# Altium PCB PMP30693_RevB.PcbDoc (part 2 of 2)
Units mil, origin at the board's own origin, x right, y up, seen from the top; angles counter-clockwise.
Board outline 2800 x 2253.94 mil, 2 copper layers (Top Layer, Bottom Layer), stack 62 mil thick; 97 components, 41 nets, 215 pads, 48 vias.
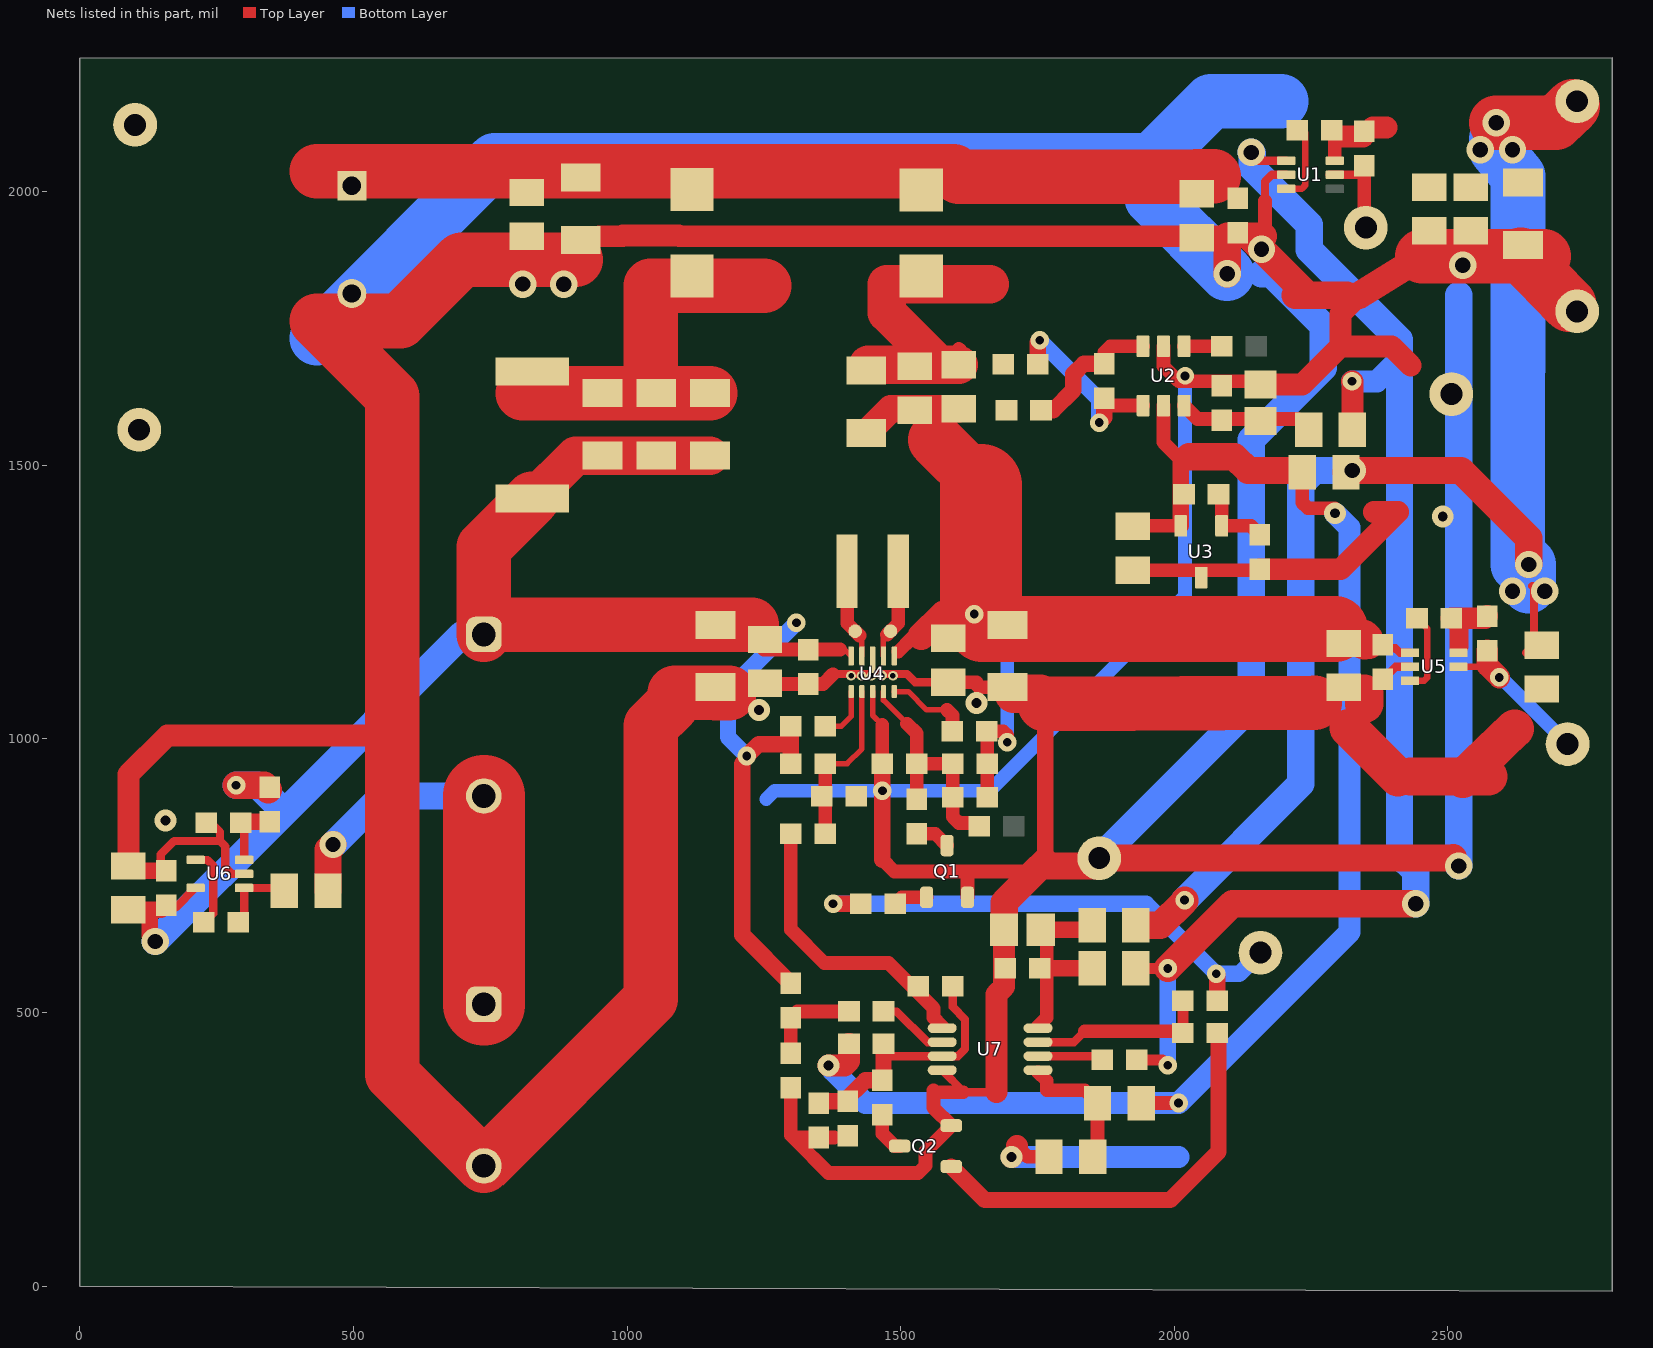
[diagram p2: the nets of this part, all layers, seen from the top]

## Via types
v1: diameter 34, hole 16, Top Layer to Bottom Layer, 18 vias
v2: diameter 50, hole 28, Top Layer to Bottom Layer, 17 vias
v3: diameter 40, hole 18, Top Layer to Bottom Layer, 7 vias
v4: diameter 18, hole 10, Top Layer to Bottom Layer, 5 vias
v5: diameter 32, hole 16, Top Layer to Bottom Layer, 1 vias

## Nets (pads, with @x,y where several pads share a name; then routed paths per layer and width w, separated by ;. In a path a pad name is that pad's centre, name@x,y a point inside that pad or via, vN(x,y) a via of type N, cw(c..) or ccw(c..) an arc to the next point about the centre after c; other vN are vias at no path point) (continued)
GND: C1.2 C2.2 C3.2 C4.2 C5.2 C6.2 C7.2 C8.2 C9.2 C10.2 C12.2 C13.2 C14.2 C15.2 C18.2 C19.2 C20.2 C21.2 C22.2 C23.2 C24.2 C25.2 C26.2 C27.2 C28.2 C29.2 Q1.2 Q2.2 R12.1 R28.1 R30.1 R32.2 R35.1 R38.1 TP4.1 TP5.1 TP6.1 TP11.1 U1.2 U2.2 U3.3 U4.3 U4.8 U5.2 U6.2 U7.4 | length 18373.7
  Top Layer w10: U4.3@1448.82,1086.61 1448.82,1043.31 1466.54,1025.59
  Top Layer w15: C19.2@147.64,759.21 147.64,788.74 172.24,813.35 255.91,813.35 ; R30.1@244.09,841.89 255.91,830.08 255.91,813.35 ; U6.2@300.2,753.31 277.56,753.31 265.75,765.12 265.75,803.5 255.91,813.35 ; 1376.36,1118.48 1511.44,1118.48 1526.22,1103.7 C21.2@1576.77,1103.7 ; U7.4@1575.79,394.68 1616.14,354.33 1675,354.33 ; 2165.62,1983.58 2165.62,2018.47 2178.38,2031.23 U1.2@2204.54,2031.23 ; C24.2@2381.25,1109.13 2404.01,1131.89 U5.2@2430.71,1131.89
  Top Layer w25: 1207.68,1101.73 C14.2@1251.97,1101.73 1253.31,1100.39 C15.2@1330.71,1100.39 1358.27,1100.39 1376.36,1118.48 ; R35.1@1299.21,362.2 1299.21,275.59 1309.06,265.75 ; 1377.95,271.65 1314.96,271.65 1309.06,265.75 ; 1466.54,779.53 1488.19,757.87 1625.98,757.87 ; R28.1@1466.54,954.72 1466.54,1025.59 ; C21.2@1576.77,1103.7 C21.2@1586.61,1103.7 1637.44,1103.7 cw(c1637.44,1102.36) 1638.78,1102.36 ccw(c1646.65,1102.36) 1646.65,1094.49 C22.2@1694.88,1094.49 ; 1614.17,354.33 1563.78,354.33 1560.04,358.07 1560.04,325.79 Q2.2@1592.52,293.31 1545.28,246.06 1545.28,219.88 1532.09,206.69 1368.11,206.69 1309.06,265.75 ; Q1.2@1622.05,710.63 1622.05,753.94 1625.98,757.87 ; 1712.6,255.91 1732.28,236.22 C29.2@1771.02,236.22 ; 1745.66,757.87 1625.98,757.87 ; C12.2@1923.86,1308.43 2154.88,1308.43 R12.1@2156.5,1310.04 ; U2.2@1980.31,1717.52 1980.31,1681.1 2007.87,1653.54 2151.57,1653.54 C9.2@2157.48,1647.64 ; v2@2162.76,1918.66 2165.62,1921.53 2165.62,1983.58
  Top Layer w30: C18.2@88.58,767.72 97.09,759.21 147.64,759.21 C19.2@157.48,759.21 ; 1466.54,779.53 v1(1466.54,905.51) R28.1@1466.54,954.72 ; 1755.28,1082.68 1763.78,1074.17 1763.78,1063.89 1763.78,775.99
  Top Layer w40: C18.2@88.58,767.72 88.58,935.04 160.18,1006.63 570.87,1006.63 ; C7.2@949.72,1918.66 991.3,1918.66 992.39,1919.75 1094.22,1919.75 1095.32,1918.66 2096.46,1918.66 ; 1675,354.33 1675,533.27 1688.98,547.24 C27.2@1688.98,651.57 ; v3(1702.76,236.22) 1712.6,246.06 1712.6,255.91 ; R12.1@2156.5,1310.04 2304.13,1310.04 2409.13,1415.04 2364.49,1415.04 ; C9.2@2157.48,1647.64 2233.9,1647.64 2303.78,1717.52 ; 2337.95,1811.02 2303.78,1776.85 2303.78,1717.52 ; 2432.09,1682.44 2397.01,1717.52 2303.78,1717.52
  Top Layer w50: C27.2@1688.98,651.57 1688.98,701.19 1745.66,757.87 1763.78,775.99 ; 1766.73,767.72 TP11.1@1862.82,767.88 ; TP11.1@1862.8,782.09 v2@2509.79,783.18 ; v2(2096.46,1850.39) 2096.46,1918.66 ; v2@2162.76,1918.66 2135.83,1918.66 2243.46,1811.02 ; 2220.96,1811.02 2243.46,1811.02 ; 2315.45,1811.02 2243.46,1811.02 ; 2337.95,1811.02 2453.12,1882.25
  Top Layer w70: C22.2@1706.69,1082.68 1755.28,1082.68 ; 2318.75,1020.1 2408.93,929.92 ; 2346.83,1064.59 2346.83,1082.68 ; 2432.09,931.25 2531.14,931.25 ; 2527.15,927.4 2531.14,931.25 ; 2573.82,931.25 2531.14,931.25 ; 2621.88,1018.75 2531.14,931.25
  Top Layer w100: 905.51,1875.98 697.35,1875.98 585.14,1763.78 433.07,1763.78 570.87,1625.98 570.87,1006.63 570.87,387.11 C25.2@738.19,219.79 1043.31,524.9 1043.31,1023.62 1082.68,1062.99 ; 1087.5,1084.43 1161.37,1084.06 C13.2@1186.07,1083.94 ; 1763.78,1063.89 2256.25,1065.9 ; 2453.12,1882.25 C5.2@2635.47,1882.25 ; C5.2@2633.23,1884.49 C5.2@2635.47,1882.25 ; 2674.94,1882.25 C5.2@2635.47,1882.25 ; TP5.1@2721.88,1793.75 C5.2@2635.47,1882.25
  Bottom Layer w25: 1254.04,889.89 1269.66,905.51 v1(1466.54,905.51) 1663.39,905.51 2019.68,1261.81 v5(2019.68,1663.39)
  Bottom Layer w40: v3(1702.76,236.22) 2007.87,236.22
  Bottom Layer w50: TP11.1@1862.8,782.09 2140.62,1059.92 2140.62,1546.88 2271.88,1678.12 2271.88,1755.37 2176.85,1850.39 2159.38,1850.39 ; v2(2519.68,767.72) 2519.68,1811.02
  Bottom Layer w100: 433.07,1732.28 757.87,2057.09 1958.66,2057.09 ; v2(2096.46,1850.39) 1958.66,1988.19 1958.66,2057.09 ; 2194.88,2165.35 2066.93,2165.35 1958.66,2057.09
  other v2: 809.38,1831.25 884.38,1830.71 2527.15,1865.62 2159.38,1894.83
  other v3: 156.25,850.76 1241.24,1053.12 1638.78,1065.76 2490.62,1406.25
  other v4: 1409.38,1115.58 1428.12,1115.58 1446.88,1115.58 1465.47,1115.85 1485.83,1115.58
NetC9_1: C9.1 C10.1 R1.1 U2.6 | length 246.1
  Top Layer w25: U2.6@2017.72,1609.25 2042.32,1584.65 2225.75,1584.65 R1.1@2245.43,1564.96
NetC11_1: C11.1 R9.2 U2.3 | length 264.4
  Top Layer w25: C11.1@1871.88,1685.63 1871.88,1706.56 1882.84,1717.52 U2.3@1942.91,1717.52
  Top Layer w30: R9.2@1756.33,1600.82 1778.95,1600.82 1815.62,1637.5 1815.62,1666.88 1834.38,1685.63 C11.1@1871.88,1685.63
NetC11_2: C11.2 R4.2 U2.4 | length 365.7
  Top Layer w25: C11.2@1871.88,1622.64 1885.26,1609.25 U2.4@1942.91,1609.25
  Top Layer w30: R4.2@1750.06,1684.72 1750.06,1724.51 v1(1754.03,1728.48) ; v1(1862.82,1578.12) 1862.82,1578.44 1871.88,1587.5 C11.2@1871.88,1622.64
  Bottom Layer w30: v1(1754.03,1728.48) 1862.82,1619.69 v1(1862.82,1578.12)
NetC13_1: C13.1 C14.1 C15.1 C17.1 C18.1 C19.1 R13.1 R14.1 R15.1 R16.1 R19.1 R21.2 R23.2 R25.1 U4.10 U6.5 | length 3416.4
  Top Layer w10: 1389.76,1163.39 1397.64,1163.39 U4.10@1409.45,1151.57
  Top Layer w15: C19.1@175.2,692.28 210.63,727.72 U6.5@211.61,727.72
  Top Layer w25: C14.1@1240.37,1173.01 1250,1163.39 C15.1@1330.71,1163.39 1389.76,1163.39
  Top Layer w30: C18.1@88.58,687.72 127.95,687.72 ; v2(137.8,629.92) 127.95,639.76 127.95,687.72 ; C19.1@157.48,696.22 148.98,687.72 127.95,687.72 ; v1@1210.63,954.72 1210.63,641.73 R23.2@1299.21,553.15 ; v1(1218.75,968.75) 1240.62,990.62 1297.76,990.62 1299.21,989.17 ; R25.1@1299.21,954.72 1299.21,989.17 ; R19.1@1299.21,1023.62 1299.21,989.17
  Top Layer w50: v1(285.43,915.35) 336.61,915.35 R21.2@344.49,907.48
  Top Layer w70: R13.1@826.77,1438.98 905.51,1517.72 R14.1@954.72,1517.72 R15.1@1053.15,1517.72 R16.1@1151.57,1517.72
  Top Layer w100: R13.1@826.77,1438.98 738.19,1350.39 C17.1@738.19,1190.94 cw(c755.91,1190.94) 755.91,1208.66 C13.1@1161.42,1208.66 1227.91,1208.66
  Bottom Layer w30: v1(1218.75,968.75) 1184.38,1003.12 1184.38,1087.5 v1(1309.38,1212.5)
  Bottom Layer w50: v2(137.8,629.92) 374.02,866.14 ; v1(285.43,915.35) 324.8,915.35 374.02,866.14 ; C17.1@738.19,1190.94 698.82,1190.94 374.02,866.14
NetC16_1: C16.1 C21.1 C22.1 C23.1 C24.1 R6.1 R7.1 R8.1 R9.1 R17.2 R20.2 U4.6 U5.1 | length 1990.3
  Top Layer w15: C24.1@2381.25,1172.12 2387.75,1165.62 2404.13,1165.62 2412.28,1157.48 U5.1@2430.71,1157.48
  Top Layer w25: 1495.47,1159.38 1519.8,1183.7 C21.1@1586.61,1183.7 ; R20.2@1657.05,1013.35 1658.2,1012.2 R17.2@1658.2,954.72 C16.1@1658.2,893.7 C16.1@1657.48,894.42 ; R20.2@1657.48,1013.78 1687.35,1013.78 1694.88,1006.25 v1(1694.88,994.09)
  Top Layer w50: R7.1@1437.01,1559.06 1481.65,1603.7 1563.69,1603.7 ; 1537.84,1187.5 1578.46,1228.12 v1(1634.38,1228.12) ; 1563.69,1546.55 1563.69,1603.7 ; R6.1@1606.3,1603.7 1563.69,1603.7 ; 2347.54,1179.76 2356.05,1171.26
  Top Layer w70: 2343.61,1183.7 2347.54,1179.76
  Top Layer w100: 1563.69,1546.55 1646.65,1463.58 ; 1648.62,1200.79 1648.96,1210.28 1649,1211.44 v1@1649.56,1227.59
  Top Layer w120: 1648.62,1200.79 2293.75,1200.79
  Top Layer w150: v1@1646.65,1228.12 1646.65,1463.58
  Bottom Layer w25: v1(1634.38,1228.12) 1694.88,1167.62 v1(1694.88,994.09)
NetC16_2: C16.2 R17.1 R24.1 R28.2 R29.2 U4.4 | length 442.1
  Top Layer w10: U4.4@1468.5,1086.61 1468.5,1070.87 1511.44,1027.93
  Top Layer w25: 1511.44,1027.93 1529.53,1009.84 R28.2@1529.53,954.72 ; R29.2@1529.53,889.76 R28.2@1529.53,954.72 ; R24.1@1643.7,836.61 1633.86,846.46 1606.3,846.46 1595.2,857.55 C16.2@1595.2,893.7 R17.1@1595.2,954.72 R28.2@1529.53,954.72
NetC17_2: C17.2 C25.1 R26.2 | length 781.4
  Top Layer w50: R26.2@453.39,722.44 453.39,797.87 v2(462.6,807.09)
  Top Layer w150: C25.1@738.19,515.06 C17.2@738.19,895.67
  Bottom Layer w50: v2(462.6,807.09) 551.18,895.67 C17.2@738.19,895.67
NetC26_1: C26.1 R36.2 R37.1 R38.2 R39.1 U7.3 | length 485
  Top Layer w15: 1469.88,420.28 U7.3@1575.79,420.28 1604.74,420.28 1617.74,433.27 1617.74,487.6 1595.28,510.06 R37.1@1595.28,548.06
  Top Layer w30: C26.1@1350,334.62 1353.12,337.75 R38.2@1396.88,337.75 ; R38.2@1403.12,337.75 R38.2@1396.88,337.75 ; R36.2@1468.5,442.91 1468.5,377.95 R39.1@1466.54,375.98 1435.11,375.98 R38.2@1396.88,337.75
NetC27_1: C27.1 C28.1 R40.2 R41.2 U7.8 | length 380.4
  Top Layer w25: U7.8@1750.98,475.1 1766.73,490.85 1766.73,580.71 1766.73,640.75 C27.1@1755.91,651.57
  Top Layer w30: C28.1@1753.94,580.71 1766.73,580.71 R41.2@1849.76,580.71 ; C27.1@1755.91,651.57 1841.89,651.57 R40.2@1849.76,659.45
NetC29_1: C29.1 R44.2 U7.5 | length 244.1
  Top Layer w25: U7.5@1750.98,391.04 1766.73,375.3 1766.73,358.07 1836.18,358.07 R44.2@1859.61,334.65 1859.61,244.8 C29.1@1851.02,236.22
NetD1_1: D1.1 R4.1 R6.2 R7.2 R8.2 | length 550.8
  Top Layer w25: 1606.3,1712.6 R6.2@1614.17,1704.72
  Top Layer w70: R7.2@1440.91,1683.7 1569.86,1683.7 ; R6.2@1606.3,1683.7 1569.86,1683.7 ; 1662.59,1830.71 1474.73,1830.71 1474.73,1778.83 1569.86,1683.7
NetD2_1: D2.1 R13.2 R14.2 R15.2 R16.2 | length 749.6
  Top Layer w100: 809.06,1631.89 R14.2@954.72,1631.89 R15.2@1053.15,1631.89 ; R16.2@1151.57,1631.89 R15.2@1053.15,1631.89 ; 1250,1828.24 1043.31,1828.24 1043.31,1641.73 R15.2@1053.15,1631.89
NetL1_1: L1.1 TP7.1 U4.9 | length 172.3
  Top Layer w10: TP7.1@1419.94,1193.75 1429.13,1184.56 U4.9@1429.13,1151.57
  Top Layer w25: L1.1@1402.17,1306.25 1402.17,1211.52 TP7.1@1424.54,1189.15
NetL1_2: L1.2 TP8.1 U4.7 | length 174.8
  Top Layer w10: U4.7@1468.5,1151.57 1468.5,1184.31 TP8.1@1481.17,1196.97
  Top Layer w25: TP8.1@1474.84,1190.64 1495.47,1211.28 L1.2@1495.47,1306.25
NetQ1_1: Q1.1 R34.1 | length 62
  Top Layer w25: R34.1@1490.16,698.82 1501.97,710.63 Q1.1@1547.24,710.63
NetQ1_3: Q1.3 R29.1 | length 64.1
  Top Layer w25: R29.1@1529.53,826.77 1562.99,826.77 Q1.3@1584.65,805.12
NetQ2_1: Q2.1 R43.2 | length 757.2
  Top Layer w30: Q2.1@1592.52,218.5 1653.54,157.48 1992.72,157.48 2080.71,245.47 R43.2@2080.71,452.76
NetQ2_3: Q2.3 R39.2 | length 75.3
  Top Layer w25: R39.2@1466.54,312.99 1466.54,278.54 1489.17,255.91 Q2.3@1498.03,255.91
NetR2_1: R2.1 TP3.1 U1.5 | length 164.5
  Top Layer w15: U1.5@2283.69,2031.23 U1.5@2293.12,2031.23 R2.1@2334.16,2031.23
  Top Layer w25: R2.1@2347.25,2047.32 2347.25,1937.13 TP3.1@2350,1934.38
NetR3_2: R3.2 U1.3 | length 150.1
  Top Layer w12: U1.3@2204.54,2005.63 2233.08,2005.63 2238.99,2011.54 2238.99,2108 R3.2@2227.18,2119.81
NetR5_2: R5.2 U2.1 | length 68.9
  Top Layer w25: U2.1@2017.72,1717.52 R5.2@2086.61,1717.52
NetR11_1: R11.1 R12.2 U3.1 | length 137
  Top Layer w25: R11.1@2080.71,1447.3 2086.61,1441.39 U3.1@2086.61,1389.41 2140.12,1389.41 R12.2@2156.5,1373.03
NetR18_1: R18.1 U6.4 | length 147.7
  Top Layer w15: U6.4@211.61,778.9 233.03,778.9 242.87,769.05 242.87,752.56 243.72,751.71 243.72,681.22 242.87,681.22 R18.1@226.38,664.72
NetR18_2: R18.2 R26.1 U6.1 | length 142.9
  Top Layer w15: R18.2@289.37,664.72 300.2,675.55 U6.1@300.2,727.72 368.11,727.72 R26.1@373.39,722.44
NetR19_2: R19.2 U4.1 | length 99.9
  Top Layer w10: R19.2@1362.2,1023.62 1391.73,1023.62 1409.45,1041.34 U4.1@1409.45,1086.61
NetR20_1: R20.1 U4.5 | length 153.8
  Top Layer w10: U4.5@1488.19,1086.61 1513.78,1086.61 1547.24,1053.15 1584.65,1053.15
  Top Layer w25: 1584.65,1053.15 1594.49,1043.31 R20.1@1594.49,1013.78
NetR21_1: R21.1 R30.2 U6.3 | length 109.8
  Top Layer w15: U6.3@300.2,778.9 R30.2@300.2,835
  Top Layer w30: R30.2@294,846.88 295.92,848.8 R21.1@346.88,848.8
NetR22_1: R22.1 TP9.1 U5.5 | length 287.6
  Top Layer w12: U5.5@2519.29,1131.89 2568.11,1131.89 2571.88,1128.12
  Top Layer w40: R22.1@2571.88,1161.42 2571.88,1134.38 v1(2593.75,1112.5)
  Bottom Layer w25: v1(2593.75,1112.5) 2596.88,1112.5 TP9.1@2718.75,990.62
NetR23_1: R23.1 R31.1 R35.2 | length 176.2
  Top Layer w25: R35.2@1299.21,425.2 R23.1@1299.21,490.16 1311.02,501.97 R31.1@1405.51,501.97
NetR25_2: R25.2 R32.1 R33.2 U4.2 | length 311
  Top Layer w10: R25.2@1362.2,954.72 1402.17,954.72 1429.13,981.69 U4.2@1429.13,1086.61
  Top Layer w25: R33.2@1362.2,826.77 1362.2,894.15 R25.2@1362.2,954.72
NetR27_2: R27.2 U5.3 | length 150
  Top Layer w12: U5.3@2430.71,1106.3 2456.3,1106.3 2462.2,1112.2 2462.2,1201.77 R27.2@2443.5,1220.47
NetR31_2: R31.2 U7.2 | length 130.5
  Top Layer w15: R31.2@1468.5,501.97 1492.64,501.97 1548.75,445.87 U7.2@1575.79,445.87
NetR33_1: R33.1 R37.2 U7.1 | length 535
  Top Layer w25: R33.1@1299.21,826.77 1299.21,651.57 1360.24,590.55 1477.56,590.55 1560.04,508.07 1560.04,490.85 U7.1@1575.79,475.1
NetR34_2: R34.2 R45.2 TP10.1 | length 950.9
  Top Layer w30: v1(1376.36,698.82) R34.2@1427.17,698.82 ; v1(2076.77,570.87) 2078.74,568.9 R45.2@2078.74,521.65
  Bottom Layer w30: v1(1376.36,698.82) 1948.82,698.82 v1(2076.77,570.87) 2118.97,570.87 TP10.1@2157.48,609.38
NetR42_2: R42.2 U7.6 | length 127.5
  Top Layer w15: U7.6@1750.98,420.28 1861.22,420.28 R42.2@1868.11,413.39
  Top Layer w20: R42.2@1862.8,408.07 R42.2@1868.11,413.39
NetR43_1: R43.1 R45.1 U7.7 | length 333.3
  Top Layer w15: U7.7@1750.98,445.87 1816.42,445.87 1836.18,465.62
  Top Layer w20: R43.1@2015.75,462.6 R45.1@2015.75,521.65
  Top Layer w25: 1836.18,465.62 2012.72,465.62 R43.1@2015.75,462.6
TL_REF: C12.1 R10.2 R11.2 R36.1 R44.1 U2.5 U3.2 | length 2657.6
  Top Layer w25: C12.1@1923.86,1388.43 1924.84,1389.41 U3.2@2011.81,1389.41 ; R44.1@1939.61,334.65 v1(2007.87,334.65) ; U2.5@1980.31,1609.25 1980.31,1541.99 2012.44,1509.87 ; R10.2@2233.62,1487.5 2233.62,1432 2243.75,1421.88 v3@2293.31,1421.88
  Top Layer w30: U3.2@2011.81,1389.41 2011.81,1509.24 2012.44,1509.87
  Top Layer w40: v3(1368.11,403.12) 1397.64,403.12 1405.51,411 R36.1@1405.51,442.91
  Top Layer w50: 2027.52,1515.62 2109.67,1515.62 2134.67,1490.62 R10.2@2218.75,1490.62
  Bottom Layer w40: v3@1376.36,393.7 1435.41,334.65 v1(2007.87,334.65) 2320.05,646.82 2320.05,1386.2 v3(2293.75,1412.5)
V_MAIN: C1.1 C2.1 C6.1 C7.1 C8.1 D1.2 D2.2 R1.2 R41.1 R42.1 TP2.1 U1.1 | length 4187.2
  Top Layer w15: v2@2140.62,2056.82 U1.1@2204.54,2056.82
  Top Layer w20: R41.1@1929.76,580.71 v1(1988.19,580.71) ; R42.1@1931.1,413.39 1978.35,413.39 v1(1988.19,403.54)
  Top Layer w40: v1(2324.8,1653.54) 2325.43,1652.91 R1.2@2325.43,1564.96
  Top Layer w50: 1596.46,2037.4 1606.3,2027.56 ; v1(1988.19,580.71) 2106.3,698.82 v2@2433.07,698.82
  Top Layer w100: 433.07,2037.4 1596.46,2037.4 ; 1606.3,2027.56 1681.58,2027.64 2041.1,2028.05 2071.84,2028.08
  Bottom Layer w30: v1(1988.19,403.54) v1(1988.19,580.71)
  Bottom Layer w40: v1(2324.8,1653.54) 2370.5,1653.54 2411.42,1694.46
  Bottom Layer w50: v2(2140.62,2071.88) 2142.53,2069.97 2142.53,2044.1 2246.88,1939.75 2246.88,1894.06 2411.42,1729.51 2411.42,1694.46 2411.42,787.4 2440.94,757.87 v2(2440.94,698.82)
V_SYS: C3.1 C4.1 C5.1 C20.1 R2.2 R3.1 R10.1 R22.2 R27.1 R40.1 TP1.1 U1.6 U5.6 | length 2898.7
  Top Layer w15: R3.1@2290.17,2119.81 R3.1@2293.12,2116.86 ; U5.6@2519.29,1157.48 2519.29,1174.46 2519.29,1180.12 ; C20.1@2643.07,1157.48 2657.48,1171.89 2657.48,1276.21 ccw(c2654.16,1276.21) 2654.16,1279.53
  Top Layer w25: 2293.12,2065.62 R3.1@2293.12,2116.86 ; 2515.62,1165.62 R27.1@2515.62,1211.44 ; 2519.29,1174.46 2525,1168.75 R27.1@2525,1201.97
  Top Layer w40: R3.1@2301.67,2100.69 R2.2@2345.19,2100.69 ; R2.2@2362.72,2117.15 2387.68,2117.15 ; R27.1@2506.5,1220.47 2567.94,1220.47 R22.2@2571.88,1224.41
  Top Layer w50: R40.1@1929.76,659.45 1974.36,659.45 2018.75,703.83 v1(2018.75,705.55) ; R10.1@2313.62,1487.5 2316.75,1490.62 v2(2325,1490.62) 2523.81,1490.62 2647.88,1366.55 v2(2647.88,1318.9)
  Top Layer w100: v2(2588.58,2125.98) 2696.85,2125.98 TP1.1@2728.12,2156.25
  Bottom Layer w50: v1(2018.75,705.55) 2231.25,918.05 2231.25,1465.62 2256.25,1490.62 v2(2325,1490.62)
  Bottom Layer w100: 2588.58,2096.46 2588.58,2077.02 2600.26,2062.58 2628.12,2028.12 ; v2@2627.72,1318.8 2627.72,1318.9 2627.95,2017.62 ; 2647.64,1279.53 v2@2647.65,1318.9
  other v2: 2618.11,1269.68 2677.17,1269.68 2559.06,2076.77 2618.11,2077.02
pads on no net: U1.4 U5.4

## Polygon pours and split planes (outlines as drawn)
NetD1_1 on Top Layer "TOP_LAYER_NETD1_1_P004" (solid, remove dead copper, pour order 4): 1357.87,1859.93 cw(c1379.19,1859.93) 1379.19,1881.25 1731.25,1881.25 cw(c1731.25,1859.38) 1753.12,1859.38 1753.12,1694.1 cw(c1743.75,1694.1) 1743.75,1684.72 1693.37,1684.72 ccw(c1693.37,1672.6) 1681.25,1672.6 cw(c1661.77,1672.6) 1661.77,1653.12 1376.62,1653.12 cw(c1376.62,1671.88) 1357.87,1671.88
NetD2_1 on Top Layer "TOP_LAYER_NETD2_1_P012" (solid, remove dead copper, pour order 12): 793.75,1580.12 cw(c793.75,1627.47) 746.39,1627.47 746.39,1703.68 cw(c780.22,1703.68) 780.22,1737.5 943.5,1737.5 ccw(c943.5,1781.5) 987.5,1781.5 987.5,1850 cw(c1021.88,1850) 1021.88,1884.38 1318.64,1884.38 cw(c1318.64,1865.62) 1337.39,1865.62 1337.39,1622.66 cw(c1295.98,1622.66) 1295.98,1581.25
GND on Top Layer "TOP_LAYER_GND_P040" (solid, remove dead copper, pour order 40): 54.81,1860.24 54.81,1892.31 cw(c106.25,1892.31) 106.25,1943.75 2756.25,1943.75 cw(c2756.25,1915.62) 2784.38,1915.62 2784.38,81.25 cw(c2750,81.25) 2750,46.88 106.25,46.88 cw(c106.25,100) 53.12,100
V_SYS on Top Layer "TOP_LAYER_V_SYS_P036" (solid, remove dead copper, pour order 36): 2705.56,1151.57 2569.53,1151.57 cw(c2569.53,1171.89) 2549.21,1171.89 2549.21,1353.35 cw(c2573.82,1353.35) 2573.82,1377.95 2673.8,1377.95 cw(c2673.8,1348.43) 2703.33,1348.43 2703.33,1166.59 cw(c2688.32,1166.59) 2688.32,1151.57
V_SYS on Top Layer "TOP_LAYER_V_SYS_P030" (solid, remove dead copper, pour order 30): 2354.93,1970.4 cw(c2354.93,2019.61) 2305.72,2019.61 2305.72,2189.96 cw(c2330.33,2189.96) 2330.33,2214.57 2637.34,2214.57 cw(c2637.34,2196.77) 2655.13,2196.77 2655.13,2002.88 cw(c2622.65,2002.88) 2622.65,1970.4
NetC13_1 on Top Layer "TOP_LAYER_NETC13_1_P024" (solid, remove dead copper, pour order 24): 1383.86,1161.42 1383.86,1188.98 ccw(c1368.11,1188.98) 1368.11,1204.72 cw(c1368.11,1224.41) 1348.43,1224.41 1348.43,1259.84 ccw(c1328.74,1259.84) 1328.74,1279.53 1294.47,1279.53 cw(c1294.47,1299.21) 1274.79,1299.21 ccw(c1274.79,1262.32) 1237.9,1262.32 1237.9,1185.33 ccw(c1259.84,1185.33) 1259.84,1163.39
NetC13_1 on Top Layer "TOP_LAYER_NETC13_1_P022" (solid, remove dead copper, pour order 22): 1279.53,1176.24 1279.53,1513.49 ccw(c1237.9,1513.49) 1237.9,1555.12 919.29,1555.12 ccw(c919.29,1525.59) 889.76,1525.59 889.76,1489.41 cw(c789.76,1489.41) 789.76,1389.41 767.72,1389.41 767.72,1183.7
V_MAIN on Top Layer "TOP_LAYER_V_MAIN_P020" (solid, remove dead copper, pour order 20): 98.43,1968.5 cw(c98.42,2017.72) 49.21,2017.72 49.21,2135.83 cw(c99.29,2154.65) 80.46,2204.72 2155.51,2214.57 cw(c2155.51,2165.35) 2204.72,2165.35 2204.72,1989.17 cw(c2184.06,1989.17) 2184.06,1968.5
NetC16_1 on Top Layer "TOP_LAYER_NETC16_1_P016" (solid, remove dead copper, pour order 16): 1676.44,1633.86 cw(c1676.44,1607.54) 1702.76,1607.54 1702.76,1474.41 cw(c1694.88,1474.41) 1694.88,1466.54 1377.95,1466.54 cw(c1377.95,1486.22) 1358.27,1486.22 1358.27,1614.17 cw(c1377.95,1614.17) 1377.95,1633.86
GND on Bottom Layer "BOTTOM_LAYER_GND_P038" (solid, remove dead copper, pour order 38): 103.12,62.5 cw(c103.12,106.25) 59.38,106.25 59.38,2156.25 cw(c121.88,2156.25) 121.88,2218.75 2737.5,2218.75 cw(c2737.5,2178.12) 2778.12,2178.12 2778.12,118.75 cw(c2721.88,118.75) 2721.88,62.5

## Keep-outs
Keep-Out Layer:
  text ".Layer_Name" at 577,-858.49 h60

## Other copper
Top Layer:
  text ".Layer_Name" at 577,-858.49 h60
Bottom Layer:
  text ".Layer_Name" at 577,-858.49 h60

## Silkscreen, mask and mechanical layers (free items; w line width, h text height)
Top Overlay:
  lines w10: 1240.62,431.25 1357.97,431.25 ; 1240.62,509.38 1359.38,509.38 ; 1340.62,456.25 1357.97,438.9 1357.97,431.25 ; 1346.88,529.23 1359.38,516.73 1359.38,509.38 ; 1357.97,431.25 1340.62,413.9 1357.97,431.25 ; 1359.38,509.38 1343.75,493.75 1359.38,509.38
  text "PMP30693_RevB" at 2018.75,87.5 h100
  text ".Layer_Name" at 577,-858.49 h60
Bottom Overlay:
  text ".Layer_Name" at 577,-858.49 h60
Top Paste:
  text ".Layer_Name" at 577,-858.49 h60
Bottom Paste:
  text ".Layer_Name" at 577,-858.49 h60
Top Solder:
  text ".Layer_Name" at 577,-858.49 h60
  text ".Layer_Name" at 577,-858.49 h60
Bottom Solder:
  text ".Layer_Name" at 577,-858.49 h60
Drill Guide:
  text ".Layer_Name" at 577,-858.49 h60
M1 Board Outline:
  the board outline again, w10
  text ".Layer_Name" at 577,-858.49 h60
M2 Board Dimensions:
  rectangle: 0,-275 125,-150
  rectangle: 125,-400 500,-275
  lines w7: 0,-275 1000,-275 ; 125,-400 125,-150 ; 250,-400 250,-150 ; 500,-400 500,-150 ; 750,-400 750,-150 ; 0,-400 1000,-400 1000,-150 0,-150 0,-400
  text ".Layer_Name" at 577,-858.49 h60
M3 3D STEP Top:
  text ".Layer_Name" at 577,-858.49 h60
M4 3D STEP Bottom:
  text ".Layer_Name" at 577,-858.49 h60
M5 Assembly Top:
  lines w10: -292,-930.17 6308,-930.17 ; -292,-726.83 6310,-726.83 ; -292,-523.5 -292,-1133.5 3713,-1133.5 6310,-1133.5 6310,-523.5 -291.5,-523.5 -291.5,-1133.5 1284,-1133.5 ; 2173,-1133.5 2173,-523.5 ; 3440,-726.83 3440,-523.5 ; 4280,-726.83 4280,-523.5 ; 4902,-1140 4902,-937.17
  text "COMPONENTS MARKED 'DNP' SHOULD NOT BE POPULATED." at 1153.5,-318.5 h60
  text "ASSEMBLY VARIANT:" at 1153,-434 h60
  text ".VariantName" at 2189,-434 h60
  text "PCB VIEWED FROM TOP SIDE" at -228.5,-655.67 h60
  text "BOARD #:" at 2248,-655.67 h60
  text ".PRJ_Number" at 2793.5,-655.67 h60
  text "REV:" at 3638,-655.67 h60
  text ".PCB_Rev" at 3929.5,-655.67 h60
  text "SVN REV:" at 4476,-655.67 h60
  text ".VersionControl_RevNumber" at 4982,-655.67 h60
  text "TID #:" at 2248,-859 h60
  text ".TID" at 2793.5,-859 h60
  text "PLOT NAME =" at -228.5,-1064.34 h60
  text ".plot_File_Name" at 577,-1064.34 h60
  text "GENERATED    :" at 2250,-1064.34 h60
  text ".Print_Date" at 3119.5,-1064.34 h60
  text ".Print_Time" at 3848.5,-1064.34 h60
  text "TEXAS INSTRUMENTS" at 5113,-1064.34 h60
M6 Assembly Bottom:
  lines w10: -292.5,-727.33 6309.5,-727.33 ; -290.5,-930.67 6309.5,-930.67 ; 1115.5,-1140.5 1115.5,-937.67 ; 1737.5,-727.33 1737.5,-524 ; 2577.5,-727.33 2577.5,-524 ; 3844.5,-1134 3844.5,-524 ; 4733.5,-1134 6309,-1134 6309,-524 -292.5,-524 -292.5,-1134 2304.5,-1134 6309.5,-1134 6309.5,-524
  text "COMPONENTS MARKED 'DNP' SHOULD NOT BE POPULATED." at 6102,-318 h60
  text ".VariantName" at 5058,-434 h60
  text "ASSEMBLY VARIANT:" at 6097,-434 h60
  text ".VersionControl_RevNumber" at 1035.5,-656.17 h60
  text "SVN REV:" at 1541.5,-656.17 h60
  text ".PCB_Rev" at 2088,-656.17 h60
  text "REV:" at 2379.5,-656.17 h60
  text ".PRJ_Number" at 3224,-656.17 h60
  text "BOARD #:" at 3769.5,-656.17 h60
  text "PCB VIEWED FROM BOTTOM SIDE" at 6246,-656.17 h60
  text ".TID" at 3224,-859.5 h60
  text "TID #:" at 3769.5,-859.5 h60
  text "TEXAS INSTRUMENTS" at 904.5,-1064.84 h60
  text ".Print_Time" at 2169,-1064.84 h60
  text ".Print_Date" at 2898,-1064.84 h60
  text "GENERATED    :" at 3767.5,-1064.84 h60
  text ".plot_File_Name" at 5440.5,-1064.84 h60
  text "PLOT NAME =" at 6246,-1064.84 h60
M9 Title Sheet:
  drawing of 57 lines, arcs and shapes, not listed
  text "1" at 739.84,8036.5 h70
  text "2" at 3235.5,8036.5 h70
  text "3" at 5724.84,8036.5 h70
  text "4" at 8231.51,8036.5 h70
  text "5" at 10730.5,8036.5 h70
  text "6" at 13235.5,8036.5 h70
  text "A" at -416.5,6893.5 h70
  text "A" at 14383.5,6893.5 h70
  text "B" at -416.5,4513.5 h70
  text "B" at 14383.5,4513.5 h70
  text "C" at -416.5,2138.5 h70
  text "C" at 14383.5,2138.5 h70
  text "PROJECT TITLE:" at 11343.5,277.5 h45
  text ".PRJ_Title" at 11393.5,144.17 h70
  text "DESIGNED FOR:" at 11343.5,-23.5 h45
  text ".PRJ_Customer" at 11393.5,-163.5 h70
  text "D" at -416.5,-231.5 h70
  text "D" at 14383.5,-231.5 h70
  text "FILE NAME:" at 11343.5,-323.5 h45
  text ".PCB_File_Name_No_Path" at 11393.5,-443.5 h70
  text "Texas Instruments (TI) and/or its licensors do not warrant the accuracy or completeness of this specification" at 6374,-605.34 h45
  text "ENGINEER:" at 11343.5,-613.5 h45
  text "LAYOUT BY:" at 12848.5,-613.5 h45
  text "or any information contained therein. TI and/or its licensors do not warrant that this design will meet" at 6329.01,-718 h45
  text ".PRJ_Engineer" at 11393.5,-768.49 h70
  text ".PCB_Layout" at 12899,-768.49 h70
  text "the specifications, will be suitable for your application or fit for any particular purpose, or will operate in" at 6329.01,-830.67 h45
  text ".Layer_Name" at 577,-858.49 h60
  text "ALTIUM DESIGNER VERSION:" at 12848.5,-923.5 h45
  text "an implementation. TI and/or its licensors do not warrant that the design is production worthy. You should" at 6329.01,-943.33 h45
  text "completely validate and test your design implementation to confirm the system functionality for your application." at 6374,-1056 h45
  text ".print_Scale" at 11393.5,-1056.83 h70
  text ".Application_BuildNumber" at 12899,-1056.83 h70
  text "1" at 739.84,-1263.5 h70
  text "2" at 3235.5,-1263.5 h70
  text "3" at 5724.84,-1263.5 h70
  text "4" at 8231.51,-1263.5 h70
  text "5" at 10730.5,-1263.5 h70
  text "6" at 13235.5,-1263.5 h70
M10 Fab Notes:
  lines w20: 11304,871 14295,871
  text ".Layer_Name" at 577,-858.49 h60
M11 Gerber Information:
  lines w10: -292,-930.17 6308,-930.17 ; -292,-726.83 6310,-726.83 ; -292,-523.5 -292,-1133.5 3713,-1133.5 6310,-1133.5 6310,-523.5 -291.5,-523.5 -291.5,-1133.5 1284,-1133.5 ; 2173,-1133.5 2173,-523.5 ; 3440,-726.83 3440,-523.5 ; 4280,-726.83 4280,-523.5 ; 4902,-1140 4902,-937.17
  text "ALL ARTWORK VIEWED FROM TOP SIDE" at -228.5,-655.67 h60
  text "BOARD #:" at 2248,-655.67 h60
  text ".PRJ_Number" at 2793.5,-655.67 h60
  text "REV:" at 3638,-655.67 h60
  text ".PCB_Rev" at 3929.5,-655.67 h60
  text "SVN REV:" at 4476,-655.67 h60
  text ".VersionControl_RevNumber" at 4982,-655.67 h60
  text "LAYER NAME =" at -228.5,-858.49 h60
  text "TID #:" at 2248,-859 h60
  text ".TID" at 2793.5,-859 h60
  text "PLOT NAME =" at -228.5,-1064.34 h60
  text ".plot_File_Name" at 577,-1064.34 h60
  text "GENERATED    :" at 2250,-1064.34 h60
  text ".Print_Date" at 3119.5,-1064.34 h60
  text ".Print_Time" at 3848.5,-1064.34 h60
  text "TEXAS INSTRUMENTS" at 5113,-1064.34 h60
M12 Stackup:
  text ".Layer_Name" at 577,-858.49 h60
M13 Component Bodies Top:
  text ".Layer_Name" at 577,-858.49 h60
M14 Component Bodies Bottom:
  text ".Layer_Name" at 577,-858.49 h60
M15 Courtyards Top:
  text ".Layer_Name" at 577,-858.49 h60
M16 Courtyards Bottom:
  text ".Layer_Name" at 577,-858.49 h60
Drill Drawing:
  text ".Layer_Name" at 577,-858.49 h60
M17 Embedded Cavity:
  text ".Layer_Name" at 577,-858.49 h60
M18 Embedded Assembly:
  text ".Layer_Name" at 577,-858.49 h60
M19 Embedded Keepout:
  text ".Layer_Name" at 577,-858.49 h60

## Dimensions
0,0 to -68.9,2244.09 on M2 Board Dimensions
0,0 to 2800,-9.38 on M2 Board Dimensions
0,-400 to 1000,-400 on M2 Board Dimensions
